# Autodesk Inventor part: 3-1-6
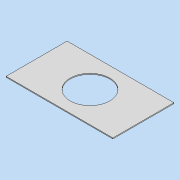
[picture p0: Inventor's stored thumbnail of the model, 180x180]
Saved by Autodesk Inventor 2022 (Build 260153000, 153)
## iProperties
Created: 2021-07
Part Number: 3-1-6
Material: 一般
Document SubType Name: Modeling
Designer: DesignLab
Density: 1 g/cm^3
Appearance: 既定
Author: DesignLab
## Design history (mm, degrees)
sketch "スケッチ1"
  geometry: L1 (0, 0)-(-350, 0); L2 (-350, 0)-(-350, -200); L3 (-350, -200)-(0, -200); L4 (0, -200)-(0, 0)
  constraints: 8 end point, 2 parallel, 1 horizontal, 1 perpendicular
  dimensions: "d0" = 350 distance of L3.end L2.end; "d1" = 200 distance of L2.end L1.end
extrude "押し出し1" new body sketch "スケッチ1" distance "d2" = 3; taper "d3" = 0 deg
sketch "スケッチ2"
  geometry: L1 (350, 200)-(0, 200) reference; L2 (0, 200)-(0, 0) reference; C1 r 65 at (175, 100); 2 further points
  constraints: 2 midpoint, 1 centre point, 1 horizontal alignment, 1 vertical alignment
  dimensions: "d4" = 130 diameter of C1
extrude "押し出し2" cut sketch "スケッチ2" distance "d7" = 3; taper "d8" = 0 deg
node "ソリッド1"
